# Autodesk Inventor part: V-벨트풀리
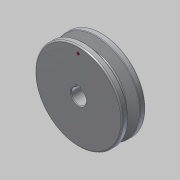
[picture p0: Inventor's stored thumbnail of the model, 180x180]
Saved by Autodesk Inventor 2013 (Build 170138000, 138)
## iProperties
Created: 2016-08
Part Number: V-벨트풀리
Material: 알루미늄 6061
Document SubType Name: Modeling
Designer: mduedu
Density: 2.71 g/cm^3
Author: mduedu
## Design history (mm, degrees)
sketch "스케치1"
  geometry: L1 (0, 9.5)-(0, -9.5); L2 (0, 9.5)-(35, 9.5); L3 (35, 9.5)-(35, 4.825); L4 (35, 4.825)-(26, 2.074); L5 (26, 2.074)-(26, 0); L6 (0, 0)-(26, 0); L7 (0, -9.5)-(35, -9.5); L8 (35, -9.5)-(35, -4.825); L9 (35, -4.825)-(26, -2.074); L10 (26, -2.074)-(26, 0); L11 (32.3, 9.5)-(32.3, -9.5); 3 further points
  constraints: 22 end point, 6 point on line, 4 perpendicular, 3 symmetric about line, 1 coincident, 1 horizontal alignment, 1 midpoint, 1 parallel, 1 vertical
  dimensions: "d0" = 19 distance of L1.start L1.end; "d2" = 70 diameter of L8 L1; "d4" = 6.3 distance between parallel lines of L10 L11; "d5" = 2.7 distance between parallel lines of L11 L8; "d6" = 8 distance of point (32.3, -4) point (32.3, 4); "d7" = 34 deg angle of L9 L4
revolve "회전1" sketch "스케치1" stored, may be unused: angle "d8" = 90 deg
sketch "스케치2"
  geometry: L1 (-2, 0)-(2, 0); L2 (2, 0)-(2, 7.8); L3 (2, 7.8)-(-2, 7.8); L4 (-2, 7.8)-(-2, 0); C1 r 6 at (0, 0); 2 further points
  constraints: 8 end point, 2 coincident, 2 parallel, 1 centre point, 1 horizontal, 1 midpoint, 1 perpendicular
  dimensions: "d9" = 12 diameter of C1; "d11" = 4 distance of L2.end L3.end; "d12" = 7.8 distance of L1.end L2.end
extrude "돌출1" cut sketch "스케치2" stored distance "d13" = 10; taper "d14" = 0 deg
sketch "스케치4"
  geometry: C1 r 22 at (0, 0); C2 r 12 at (0, 0); 1 further point
  constraints: 2 centre point, 2 coincident
  dimensions: "d32" = 44 diameter of C1; "d34" = 24 diameter of C2
extrude "돌출2" cut sketch "스케치4" distance "d35" = 12; taper "d36" = 0 deg
fillet "모깎기1" dims "d20" = 0.5, "d21" = 1, "d37" = 1
fillet "모깎기6" dims "d38" = 3
chamfer "모따기1" distance "d26" = 0.5; stored, may be unused: second distance "d27" = 2, angle "d28" = 45 deg
sketch "스케치5" dims "d39" = 60
  geometry: C1 r 1 at (0, 30); 2 further points
  constraints: 2 vertical alignment, 1 centre point, 1 coincident, 2 other
  dimensions: "d40" = 2 diameter of C1
extrude "돌출3" join sketch "스케치5" distance "d41" = 0.5; taper "d42" = 0 deg
node "솔리드1"
